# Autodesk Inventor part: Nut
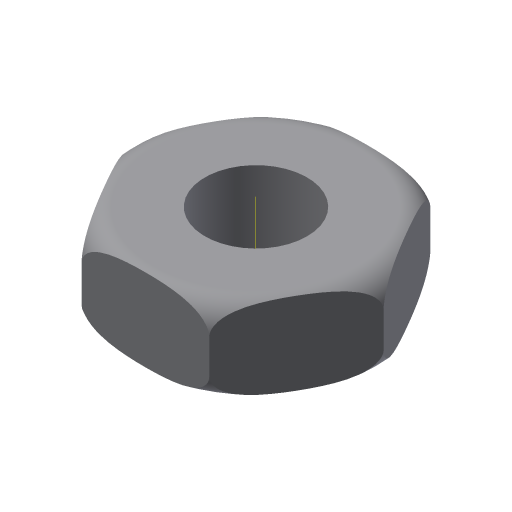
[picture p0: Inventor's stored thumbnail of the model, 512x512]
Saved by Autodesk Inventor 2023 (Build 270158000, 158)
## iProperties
Created: 2009-04
Part Number: Nut
Document SubType Name: Modeling
Designer: Sham
Density: 1 g/cm^3
Material: Generic
Appearance: Default
Mass: 4.65064 g
Surface Area: 21.3319 cm^2
Volume: 4.65064 cm^3
Author: Sham
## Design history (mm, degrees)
sketch "Sketch1"
  geometry: L1 (7.5, 12.99)-(15, 0); L2 (15, 0)-(7.5, -12.99); L3 (7.5, -12.99)-(-7.5, -12.99); L4 (-7.5, -12.99)-(-15, 0); L5 (-15, 0)-(-7.5, 12.99); L6 (-7.5, 12.99)-(7.5, 12.99); C1 r 6 at (0, 0); 1 further point
  constraints: 12 end point, 1 centre point, 1 coincident, 13 other
  dimensions: "d0" = 30 distance of L1.end L4.end; "d1" = 12 diameter of C1
extrude "Extrusion1" new body sketch "Sketch1" distance "d2" = 12; taper "d3" = 0 deg
sketch "Sketch2"
  geometry: L1 (-12, 0)-(-12, -0.022); L2 (-15, 7)-(-15, 3); L3 (0, -2.87)-(0, 12.87) reference; A1 r 3 centre (-12, 7) between (-12, 10) and (-15, 7); A2 r 3 centre (-12, 3) between (-15, 3) and (-12, 0)
  constraints: 4 end point, 4 point on circle, 2 centre point, 1 tangent
revolve "Revolution1" sketch "Sketch2" stored, may be unused: angle "d7" = 90 deg
body "Solid1"
other parameters: "d6" = 90 deg
